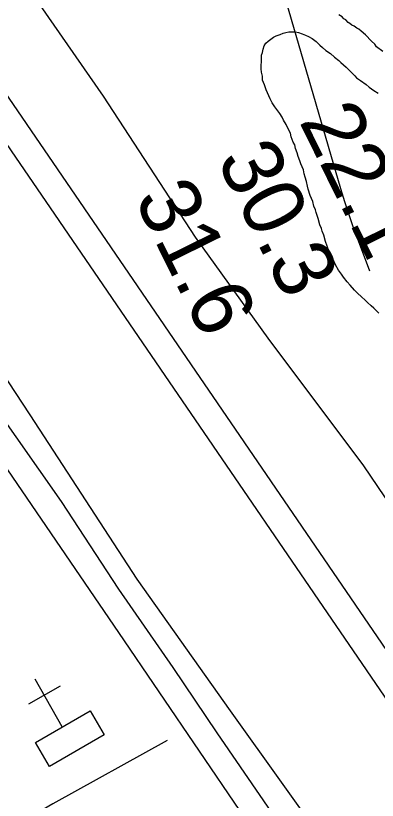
# Model space of a CAD drawing. Extents: x 3297753 to 3335611, y 652252 to 677623.
# Drawn here: x 3307898 to 3308295, y 670586 to 671447 of the extents above; entities that cross this region are included whole.
import ezdxf

# ---------------------------------------------------------------- set-up
doc = ezdxf.new("R2010")
doc.units = 0
for name, color, linetype in [('V-BLDG-OTLN', 7, 'Continuous'), ('V-LEVE-TOET', 7, 'Continuous'), ('V-RIVR-EDGE', 7, 'Continuous'), ('V-RIVR-RANG', 7, 'Continuous'), ('V-ROAD-CNTR', 7, 'Continuous'), ('V-SITE-OTLN', 7, 'Continuous'), ('V-SITE-VEGE', 7, 'Continuous'), ('V-SURV-LINE', 7, 'Continuous'), ('V-TOPO-MAJR', 7, 'Continuous'), ('V-TOPO-SHOR', 7, 'Continuous')]:
    doc.layers.add(name, color=color, linetype=linetype)

msp = doc.modelspace()

# ---------------------------------------------------------------- linework, layer by layer
at = {"layer": 'V-BLDG-OTLN'}
msp.add_lwpolyline([(3307994.84, 670657.54), (3307935, 670622.72), (3307919.66, 670649.09), (3307979.49, 670683.91)], close=True, dxfattribs=at)
at = {"layer": 'V-LEVE-TOET'}
for points in [[(3307494.7, 672830.64), (3307521.16, 672727.29), (3307556, 672592.74), (3307595.6, 672445.65), (3307636.04, 672297.65), (3307671.66, 672140.15), (3307699.46, 672005.9), (3307716.55, 671951.41), (3307766.23, 671772.17), (3307787, 671700.79), (3307825.15, 671623.38), (3307900.71, 671493.27), (3307993.72, 671358.9), (3308094.67, 671203.93), (3308174.58, 671093.02), (3308279.68, 670952.85), (3308372.58, 670815.84), (3308495.25, 670632.62), (3308581.29, 670500.31)], [(3307372.46, 672447.21), (3307426.69, 672208.73), (3307478.91, 671985.32), (3307541.85, 671723.55), (3307567.44, 671620.24), (3307587.91, 671541.82), (3307598.69, 671505.23), (3307614.72, 671467.54), (3307657.23, 671389.06), (3307780.96, 671210.21), (3307913.44, 671008.95), (3308030.94, 670828.6), (3308133.21, 670684.14), (3308250.51, 670519.66)]]:
    msp.add_lwpolyline(points, dxfattribs=at)
at = {"layer": 'V-RIVR-EDGE'}
msp.add_spline([(3307850.62, 675821), (3307850.75, 675819.26), (3307852.36, 675798.53), (3307852.34, 675791.07), (3307856.9, 675791.47), (3307860.2, 675784), (3307858.08, 675766.6), (3307858.03, 675745.87), (3307859.68, 675743.8), (3307863.41, 675742.96), (3307863.4, 675739.64), (3307862.94, 675720.99), (3307866.19, 675694.04), (3307864.47, 675668.35), (3307864.85, 675653.43), (3307866.04, 675632.29), (3307865.98, 675608.25), (3307860.93, 675578), (3307855.03, 675536.15), (3307852.01, 675490.98), (3307848.61, 675457.42), (3307845.62, 675420.95), (3307843.09, 675401.89), (3307841.81, 675387.8), (3307842.17, 675364.59), (3307841.69, 675337.23), (3307844.13, 675320.65), (3307845.74, 675299.92), (3307848.96, 675263.02), (3307851.37, 675230.27), (3307851.72, 675204.99), (3307854.14, 675179.28), (3307856.98, 675153.99), (3307856.53, 675138.24), (3307855.69, 675135.76), (3307856.07, 675118.35), (3307855.63, 675111.72), (3307854.35, 675095.97), (3307852.65, 675077.74), (3307852.18, 675054.11), (3307855.44, 675031.72), (3307862.38, 674991.5), (3307864.8, 674962.48), (3307868.44, 674926), (3307870.05, 674906.1), (3307872.46, 674875.01), (3307874.08, 674859.25), (3307876.52, 674843.5), (3307878.94, 674816.13), (3307882.53, 674757.68), (3307886.15, 674712.5), (3307885.71, 674704.21), (3307884.45, 674697.99), (3307884.44, 674691.78), (3307887.31, 674680.16), (3307887.28, 674668.97), (3307887.26, 674658.2), (3307885.58, 674651.15), (3307881.01, 674644.12), (3307881, 674639.97), (3307886.35, 674626.28), (3307890.03, 674605.55), (3307895.77, 674578.59), (3307899.43, 674550.81), (3307909.27, 674510.58), (3307914.59, 674481.97), (3307918.25, 674453.78), (3307918.22, 674440.51), (3307919.86, 674433.88), (3307927.3, 674423.08), (3307927.28, 674417.7), (3307927.25, 674404.02), (3307928.48, 674400.28), (3307931.78, 674393.23), (3307935.06, 674376.64), (3307944.54, 674357.55), (3307954.85, 674337.22), (3307963.92, 674316.06), (3307975.42, 674271.68), (3307986.49, 674225.23), (3308000.06, 674178.77), (3308007.44, 674148.91), (3308015.22, 674108.27), (3308020.53, 674078.42), (3308024.25, 674072.19), (3308025.04, 674059.34), (3308025.41, 674039.44), (3308027.79, 673997.16), (3308030.63, 673971.46), (3308027.69, 673955.3), (3308027.24, 673943.28), (3308027.64, 673935.82), (3308029.69, 673925.45), (3308035.46, 673911.76), (3308035.42, 673899.32), (3308034.12, 673873.21), (3308036.13, 673851.24), (3308038.54, 673818.91), (3308040.98, 673799), (3308046.76, 673788.21), (3308050.46, 673778.26), (3308048.79, 673772.46), (3308048.76, 673761.27), (3308053.68, 673740.53), (3308060.66, 673711.09), (3308069.7, 673678.73), (3308069.66, 673665.06), (3308067.15, 673653.46), (3308067.55, 673650.14), (3308072.94, 673649.3), (3308077.91, 673648.87), (3308079.98, 673646.38), (3308086.52, 673608.64), (3308091.84, 673582.1), (3308104.58, 673536.48), (3308114.83, 673495), (3308121.38, 673461), (3308123.83, 673446.07), (3308127.95, 673436.12), (3308140.31, 673406.24), (3308148.95, 673377.21), (3308153.04, 673357.72), (3308158.34, 673321.23), (3308169, 673273.12), (3308189.1, 673188.1), (3308196.88, 673150.37), (3308207.96, 673103.92), (3308212.04, 673079.45), (3308214.06, 673059.97), (3308216.51, 673045.04), (3308218.98, 673035.91), (3308226, 673025.53), (3308228.46, 673015.99), (3308228.43, 673002.32), (3308230.49, 672996.92), (3308235.04, 672992.77), (3308235.02, 672984.48), (3308237.47, 672972.87), (3308241.99, 672953.37), (3308247.32, 672933.05), (3308253.9, 672910.65), (3308257.61, 672901.53), (3308263.8, 672890.32), (3308276.17, 672865), (3308277.39, 672856.3), (3308278.62, 672850.08), (3308283.16, 672844.26), (3308286.05, 672839.7), (3308286.04, 672832.24), (3308285.59, 672818.97), (3308288.47, 672812.33), (3308293.83, 672800.3), (3308303.72, 672777.89), (3308309.9, 672762.54), (3308316.07, 672743.05), (3308316.44, 672725.64), (3308318.1, 672723.15), (3308323.06, 672717.33), (3308327.59, 672706.13), (3308331.69, 672690.37), (3308330.84, 672679.6), (3308330.4, 672672.14), (3308332.46, 672667.16), (3308337.42, 672658.44), (3308343.59, 672642.67), (3308347.7, 672625.26), (3308355.91, 672595.39), (3308355.89, 672584.62), (3308357.53, 672579.64), (3308362.07, 672570.92), (3308366.61, 672563.45), (3308376.07, 672534), (3308399.56, 672478.4), (3308411.51, 672452.67), (3308418.52, 672435.25), (3308421.79, 672418.66), (3308423.01, 672409.95), (3308425.49, 672403.73), (3308428.79, 672397.5), (3308430.01, 672387.55), (3308434.95, 672375.52), (3308444.41, 672344.83), (3308450.58, 672326.99), (3308456.78, 672320.76), (3308459.66, 672312.87), (3308465.4, 672287.99), (3308467.43, 672268.09), (3308473.18, 672249.01), (3308476.05, 672236.57), (3308485.95, 672214.16), (3308490.05, 672198.81), (3308495.86, 672201.7), (3308496.67, 672193), (3308499.08, 672161.9), (3308505.23, 672134.53), (3308513.87, 672107.57), (3308522.52, 672084.75), (3308527.9, 672082.25), (3308536.2, 672087.2), (3308540.76, 672086.78), (3308539.51, 672083.88), (3308535.76, 672077.67), (3308534.91, 672067.73), (3308534.47, 672059.44), (3308531.96, 672050.74), (3308533.2, 672047.42), (3308536.91, 672037.88), (3308550.93, 672008.42), (3308564.93, 671974.39), (3308569.87, 671959.46), (3308576.49, 671954.88), (3308585.14, 671932.48), (3308595.86, 671910.49), (3308604.94, 671895.13), (3308605.76, 671888.49), (3308607.82, 671885.17), (3308610.71, 671881.02), (3308616.47, 671862.77), (3308627.6, 671838.7), (3308640.39, 671816.29), (3308660.99, 671765.26), (3308672.95, 671740.77), (3308685.32, 671715.46), (3308698.53, 671692.21), (3308700.17, 671685.58), (3308711.29, 671658.19), (3308728.21, 671627.9), (3308743.07, 671602.99), (3308758.34, 671575.6), (3308771.97, 671554.84), (3308775.27, 671548.61), (3308783.11, 671536.16), (3308790.54, 671522.88), (3308793.43, 671519.55), (3308797.16, 671517.06), (3308801.29, 671511.24), (3308803.76, 671502.95), (3308810.8, 671502.1), (3308815.77, 671499.19), (3308833.53, 671474.28), (3308845.09, 671458.5), (3308857.08, 671443.55), (3308870.72, 671429.01), (3308882.71, 671418.61), (3308908.77, 671397), (3308930.27, 671375.39), (3308944.33, 671361.26), (3308952.58, 671346.74), (3308960.43, 671336.77), (3308966.22, 671331.78), (3308972.85, 671328.86), (3308985.64, 671307.28), (3309001.75, 671282.37), (3309010.84, 671271.57), (3309010.83, 671268.25), (3309008.34, 671266.19), (3309011.64, 671262.03), (3309018.66, 671250.83), (3309024.85, 671237.13), (3309035.15, 671212.24), (3309059.5, 671169.07), (3309066.5, 671150.82), (3309067.71, 671140.45), (3309071.85, 671135.88), (3309077.22, 671128.41), (3309078.45, 671123.02), (3309078.43, 671117.63), (3309082.15, 671111.4), (3309089.15, 671092.73), (3309098.63, 671073.23), (3309111.41, 671045.01), (3309116.36, 671032.15), (3309123.35, 671011), (3309128.7, 670995.65), (3309133.23, 670984.86), (3309143.97, 670967.42), (3309159.66, 670945.42), (3309169.17, 670933.37), (3309181.99, 670924.22), (3309188.19, 670917.16), (3309197.69, 670902.22), (3309217.1, 670874.81), (3309231.57, 670859.03), (3309239.82, 670845.33), (3309244.79, 670840.76), (3309252.23, 670835.35), (3309260.51, 670831.18), (3309275.4, 670817.06), (3309282.43, 670810.41), (3309290.69, 670800.02), (3309303.1, 670788.39), (3309315.92, 670775.51), (3309335.34, 670751), (3309344.42, 670736.47), (3309351.03, 670726.51), (3309360.13, 670721.51), (3309375.84, 670704.9), (3309390.72, 670688.69), (3309403.11, 670668.77), (3309415.49, 670646.77), (3309426.65, 670635.14), (3309442.78, 670618.52), (3309454.34, 670603.15), (3309462.18, 670588.63), (3309470.85, 670575.34), (3309476.63, 670563.31), (3309487.39, 670558.31), (3309488.62, 670554.57), (3309489.44, 670550.84), (3309494.82, 670544.2), (3309506.81, 670533.39), (3309523.77, 670518.84), (3309529.95, 670505.98), (3309538.6, 670484.82), (3309549.72, 670453.7), (3309551.35, 670440.85), (3309555.47, 670430.89), (3309568.67, 670408.89), (3309577.35, 670396.02), (3309581.47, 670386.48), (3309581.46, 670383.16), (3309578.55, 670379.85), (3309576.88, 670374.88), (3309582.24, 670364.09), (3309594.61, 670336.71), (3309604.49, 670308.91), (3309606.94, 670296.06), (3309614.38, 670284.85), (3309627.18, 670266.99), (3309635.46, 670261.59), (3309639.18, 670259.92), (3309638.74, 670249.97), (3309639.54, 670236.29), (3309641.18, 670228), (3309644.89, 670221.36), (3309656.46, 670208.06), (3309664.31, 670195.61), (3309663.46, 670188.15), (3309663.84, 670176.13), (3309667.96, 670166.17), (3309673.34, 670159.94), (3309684.07, 670142.92), (3309690.66, 670126.33), (3309700.14, 670102.68), (3309716.65, 670076.52)], degree=3, dxfattribs=at)
at = {"layer": 'V-ROAD-CNTR'}
msp.add_lwpolyline([(3307339.14, 672310.87), (3307407.41, 672029.86), (3307476.95, 671732.57), (3307511.07, 671600.1), (3307529.82, 671540.23), (3307554.17, 671481.54), (3307565.65, 671454.66), (3307628.51, 671339.43), (3307687.48, 671244.51), (3307819.52, 671049.73), (3308010.54, 670769.93), (3308276.08, 670379.16), (3308519.64, 670019.78), (3308575.25, 669936.41), (3308626.7, 669864.47), (3308662.44, 669815.55), (3308701.66, 669766.43), (3308749.57, 669726.83), (3308879.73, 669615.8), (3309312.15, 669283.51), (3309781.29, 668929.63), (3310172.08, 668625.19)], dxfattribs=at)
at = {"layer": 'V-SITE-OTLN'}
for p, q in [((3307948.82, 670666.37), (3307919.39, 670718.65)), ((3307946.63, 670711.03), (3307911.77, 670691.42))]:
    msp.add_line(p, q, dxfattribs=at)
at = {"layer": 'V-SITE-VEGE'}
msp.add_lwpolyline([(3308300.61, 671407.65), (3308293.98, 671412.83), (3308292.15, 671415.84), (3308288.36, 671418.94), (3308281.81, 671426.07), (3308277.09, 671430.18), (3308274.25, 671432.26), (3308272.33, 671433.32), (3308269.48, 671435.4), (3308266.59, 671436.5), (3308264.72, 671438.54), (3308262.81, 671439.6), (3308260, 671442.65), (3308258.09, 671443.71), (3308256.22, 671445.75), (3308252.39, 671447.87)], dxfattribs=at)
at = {"layer": 'V-SURV-LINE'}
for points in [[(3307777.67, 671521.09), (3308611.79, 670301.17)], [(3308587.02, 670284.24), (3307752.9, 671504.17)]]:
    msp.add_lwpolyline(points, dxfattribs=at)
at = {"layer": 'V-TOPO-MAJR'}
msp.add_lwpolyline([(3308132.48, 671675.87), (3308254.37, 671257.51), (3308258.77, 671243.06), (3308263.39, 671228.69), (3308268.37, 671214.44), (3308273.57, 671200.26), (3308286.27, 671166.88)], dxfattribs=at)
at = {"layer": 'V-TOPO-SHOR'}
for points in [[(3307501.52, 671756.93), (3307522.84, 671670.87), (3307549.05, 671573.34), (3307570.79, 671508.8), (3307596.66, 671449.46), (3307620.56, 671401.47), (3307651.16, 671349.76), (3307683.37, 671301.41), (3307737.05, 671216.92), (3307790.17, 671142.23), (3307815.79, 671100.03), (3307872.61, 671020.3), (3307947.88, 670913.84), (3308010.85, 670817.7), (3308070.34, 670731.49), (3308118.69, 670659.94), (3308182.77, 670566.68), (3308240.26, 670479.58), (3308290.54, 670397.97)], [(3308215.44, 671269.85), (3308214.27, 671273.42), (3308213.57, 671277.86), (3308212.38, 671280.99), (3308210.77, 671284.59), (3308209.58, 671287.72), (3308208.03, 671292.63), (3308206.88, 671296.65), (3308204.87, 671301.14), (3308204.15, 671305.14), (3308202.52, 671308.29), (3308200.13, 671314.12), (3308199.42, 671318.11), (3308196.56, 671323.52), (3308194.53, 671327.58), (3308191.66, 671332.55), (3308190.46, 671335.68), (3308187.56, 671339.77), (3308185.47, 671342.5), (3308182.13, 671347.05), (3308179.24, 671351.58), (3308177.21, 671355.63), (3308175.6, 671359.22), (3308172.78, 671365.51), (3308170.83, 671371.32), (3308168.83, 671376.25), (3308168.58, 671380.67), (3308167.44, 671385.13), (3308167.15, 671388.67), (3308167.34, 671393.06), (3308167.47, 671396.14), (3308167.62, 671399.66), (3308167.79, 671403.62), (3308168.79, 671406.66), (3308169.39, 671410.16), (3308170.43, 671414.08), (3308172.32, 671417.08), (3308175.06, 671419.17), (3308177.79, 671421.26), (3308180.96, 671423.33), (3308183.67, 671424.98), (3308188.15, 671426.55), (3308191.28, 671427.74), (3308194.4, 671428.49), (3308197.51, 671429.24), (3308201.93, 671429.49), (3308205.01, 671429.36), (3308208.07, 671428.79), (3308212.41, 671427.28), (3308215.88, 671425.82), (3308219.34, 671424.35), (3308223.2, 671421.98), (3308227.47, 671418.71), (3308231.7, 671414.57), (3308234.69, 671412.24), (3308238.08, 671409.01), (3308243.23, 671405.71), (3308247.9, 671401.55), (3308252.58, 671397.82), (3308254.69, 671395.53), (3308257.68, 671393.2), (3308260.64, 671390.43), (3308265.72, 671385.37), (3308269.95, 671381.22), (3308272.05, 671378.93), (3308276.34, 671376.11), (3308282.31, 671371.45), (3308285.72, 671368.66), (3308290.85, 671364.92), (3308295.58, 671362.07)], [(3308296.36, 671120.57), (3308294.25, 671122.86), (3308290.86, 671126.09), (3308287.88, 671128.42), (3308284.07, 671132.1), (3308281.12, 671135.31), (3308277.71, 671138.1), (3308272.62, 671142.72), (3308269.67, 671145.93), (3308265.06, 671151.42), (3308261.69, 671155.08), (3308257.49, 671160.11), (3308255.43, 671163.28), (3308252.09, 671167.83), (3308248.82, 671173.7), (3308247.19, 671176.85), (3308244.77, 671182.24), (3308243.58, 671185.37), (3308240.73, 671190.78), (3308239.54, 671193.92), (3308238, 671199.27), (3308236.08, 671205.96), (3308234.07, 671210.45), (3308233.32, 671213.57), (3308231.73, 671217.6), (3308229.81, 671224.29), (3308227.45, 671231), (3308226.7, 671234.12), (3308225.11, 671238.15), (3308224, 671243.05), (3308221.2, 671249.78), (3308218.84, 671256.48), (3308218.1, 671260.04), (3308216.99, 671264.94), (3308215.44, 671269.85)], [(3308064.15, 670651.31), (3307938.5, 670581.74), (3307837.19, 670522.69), (3307738.98, 670461.51), (3307636.52, 670403.3), (3307511.92, 670330.49), (3307414.28, 670273.28), (3307301.14, 670207.56), (3307176.53, 670134.35), (3307081.62, 670075.82), (3306992.78, 670019.43), (3306956.52, 670000.65)]]:
    msp.add_lwpolyline(points, dxfattribs=at)

# ---------------------------------------------------------------- texts
at = {"layer": 'V-RIVR-RANG'}
for s, p in [('22.1', (3308208.36, 671331.43)), ('30.3', (3308117.74, 671289.08)), ('31.6', (3308027.36, 671246.26))]:
    msp.add_text(s, height=67, rotation=296.26833, dxfattribs=at).set_placement(p)

doc.saveas('drawing.dxf')
